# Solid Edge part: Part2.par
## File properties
Author: Vicky Raina
Template: Normal.par
Last saved by: Robert a Rhodes jr
Revision: 11
Application: Solid Edge
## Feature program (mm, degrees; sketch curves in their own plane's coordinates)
sketch for "unnamed Protrusion 1" plane through (0, 0, 0) normal (0, -1, 0) x-axis (1, 0, 0)
  line (-41.5864, -1.056) -> (-41.5864, 10.944)
  line (-41.5864, 10.944) -> (58.4136, 10.944)
  arc centre (58.4136, 25.944) radius 15 from (58.4136, 10.944) to (70.6346, 34.6415) ccw
  line (70.6346, 34.6415) -> (76.9484, 45.5772)
  arc centre (58.4136, 25.944) radius 27 from (58.4136, -1.056) to (76.9484, 45.5772) ccw
  line (58.4136, -1.056) -> (-41.5864, -1.056)
extrude "unnamed Protrusion 1" add finite 50 along +normal
sketch for "unnamed Protrusion 2" #1 plane through (-44.5864, -25, 4.1402) normal (-0.866025, 0, -0.5) x-axis (0, -1, 0)
  line (-15, 28) -> (-15, 73)
  arc centre (-10, 73) radius 5 from (-5, 73) to (-15, 73) ccw
  line (-5, 73) -> (-5, 36)
  line (-5, 36) -> (5, 36)
  line (5, 36) -> (5, 61)
  arc centre (10, 61) radius 5 from (5, 61) to (15, 61) cw
  line (15, 61) -> (15, 28)
  arc centre (0, 28) radius 15 from (-15, 28) to (15, 28) ccw
sketch for "unnamed Protrusion 2" #2 plane through (-44.5864, -25, 4.1402) normal (-0.866025, 0, -0.5) x-axis (0, -1, 0)
  arc centre (-19, 84) radius 6 from (-25, 84) to (-16.2055, 89.3095) cw
  line (-16.2055, 89.3095) -> (21.7945, 69.3095)
  arc centre (19, 64) radius 6 from (21.7945, 69.3095) to (25, 64) cw
  line (25, 64) -> (25, -6)
  line (25, -6) -> (-25, -6)
  line (-25, 84) -> (-25, -6)
extrude "unnamed Protrusion 2" add finite 12 along -normal
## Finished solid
Body 1: solid body, 20 faces, 54 edges, 36 vertices.
  Faces by surface: plane 13, cylinder 7
  Edges by curve: line 40, circle 14
Bounding box of the edges (mm): 175.000 x 50.000 x 89.138, from (-89.5864, -50, -1.056) to (85.4136, 0, 88.0824).
Cylindrical faces by radius (mm): R5 x2, R6 x2, R15 x2, R27 x1
Planar faces by outward normal: +y 3, +z 1, -y 3, -z 1, oblique 5
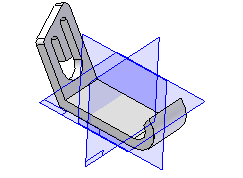
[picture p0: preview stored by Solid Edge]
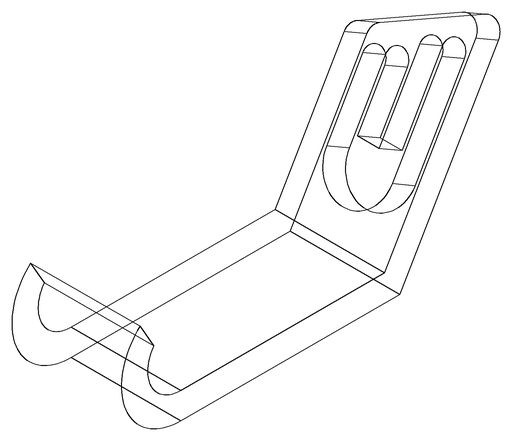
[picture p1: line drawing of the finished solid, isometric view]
